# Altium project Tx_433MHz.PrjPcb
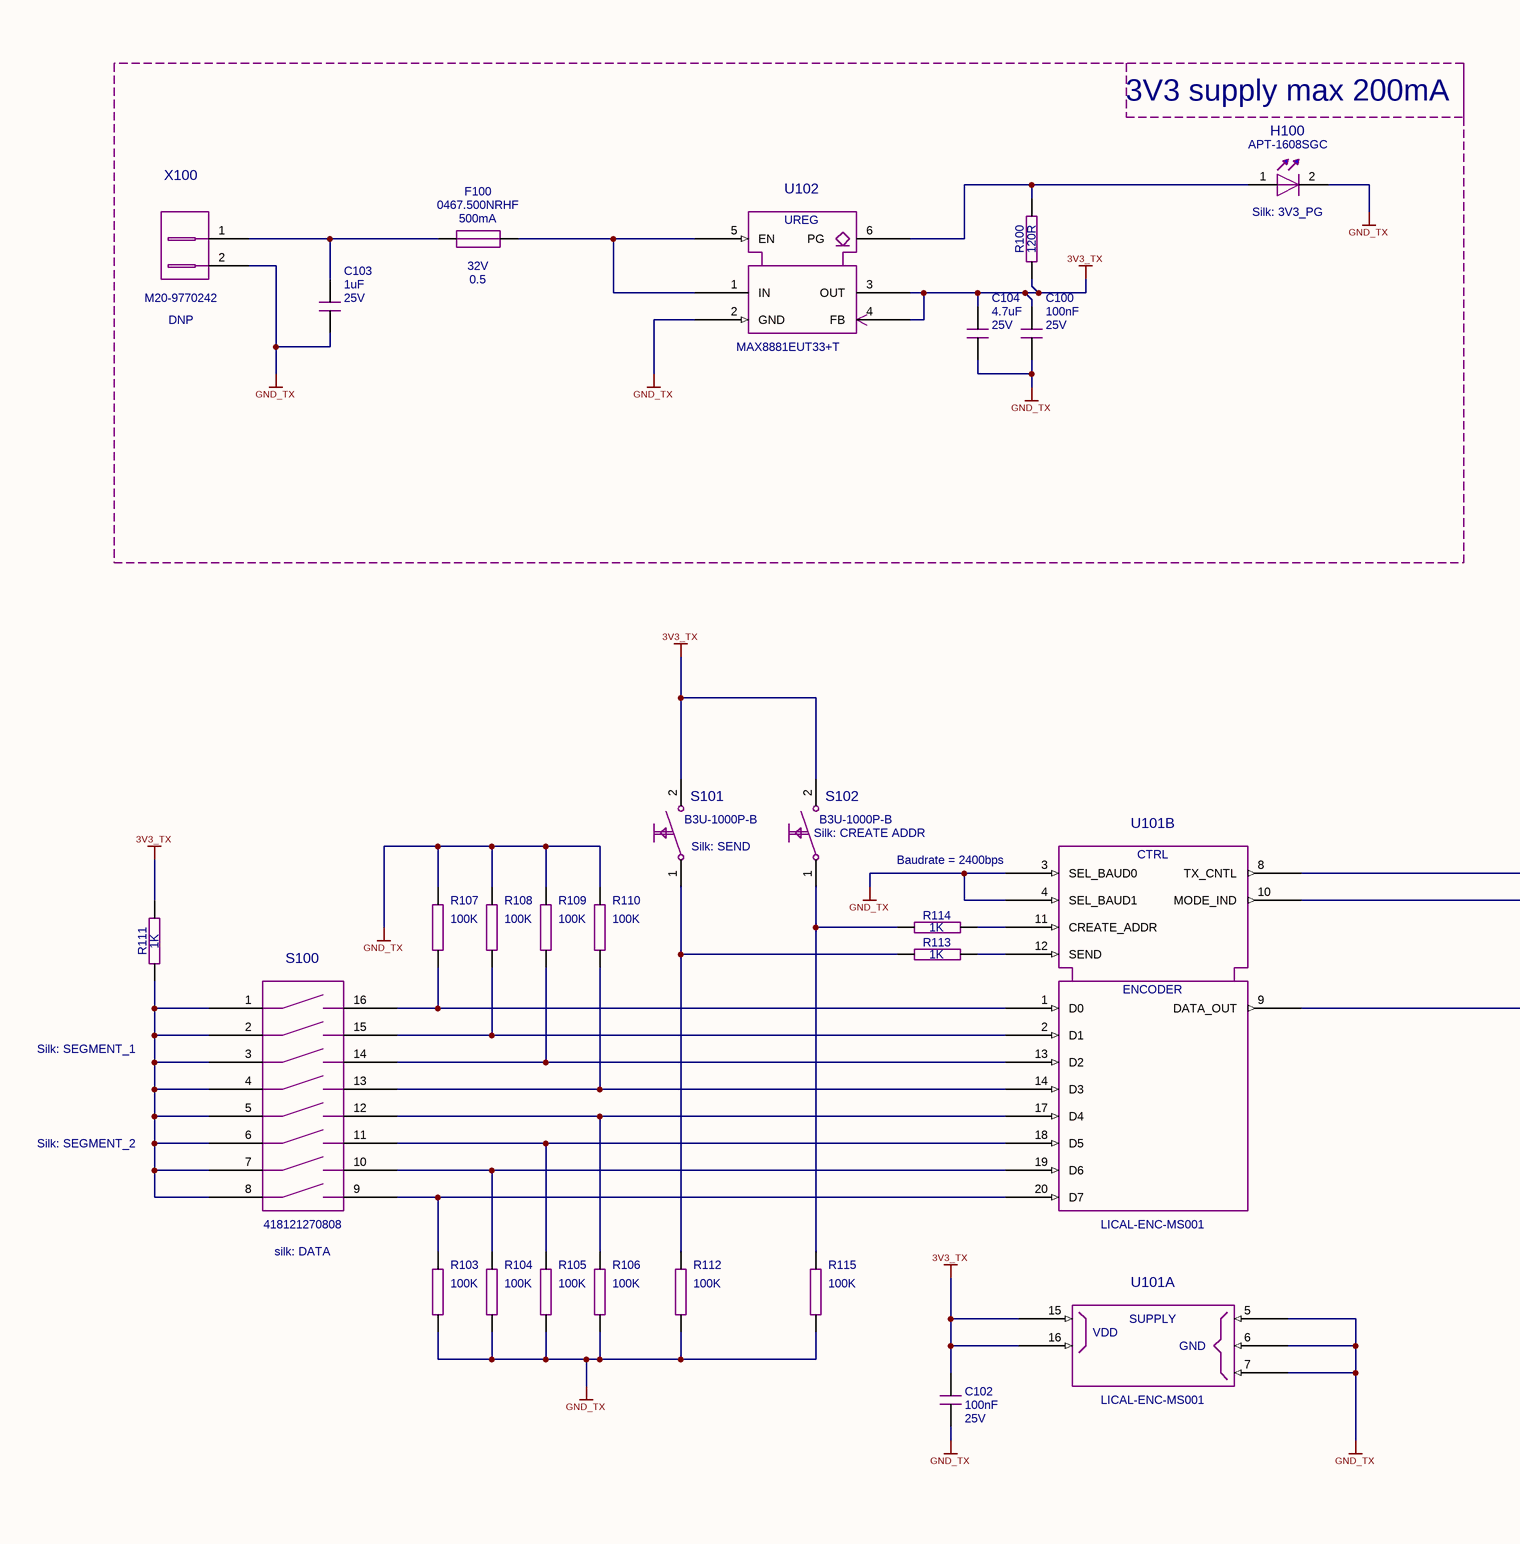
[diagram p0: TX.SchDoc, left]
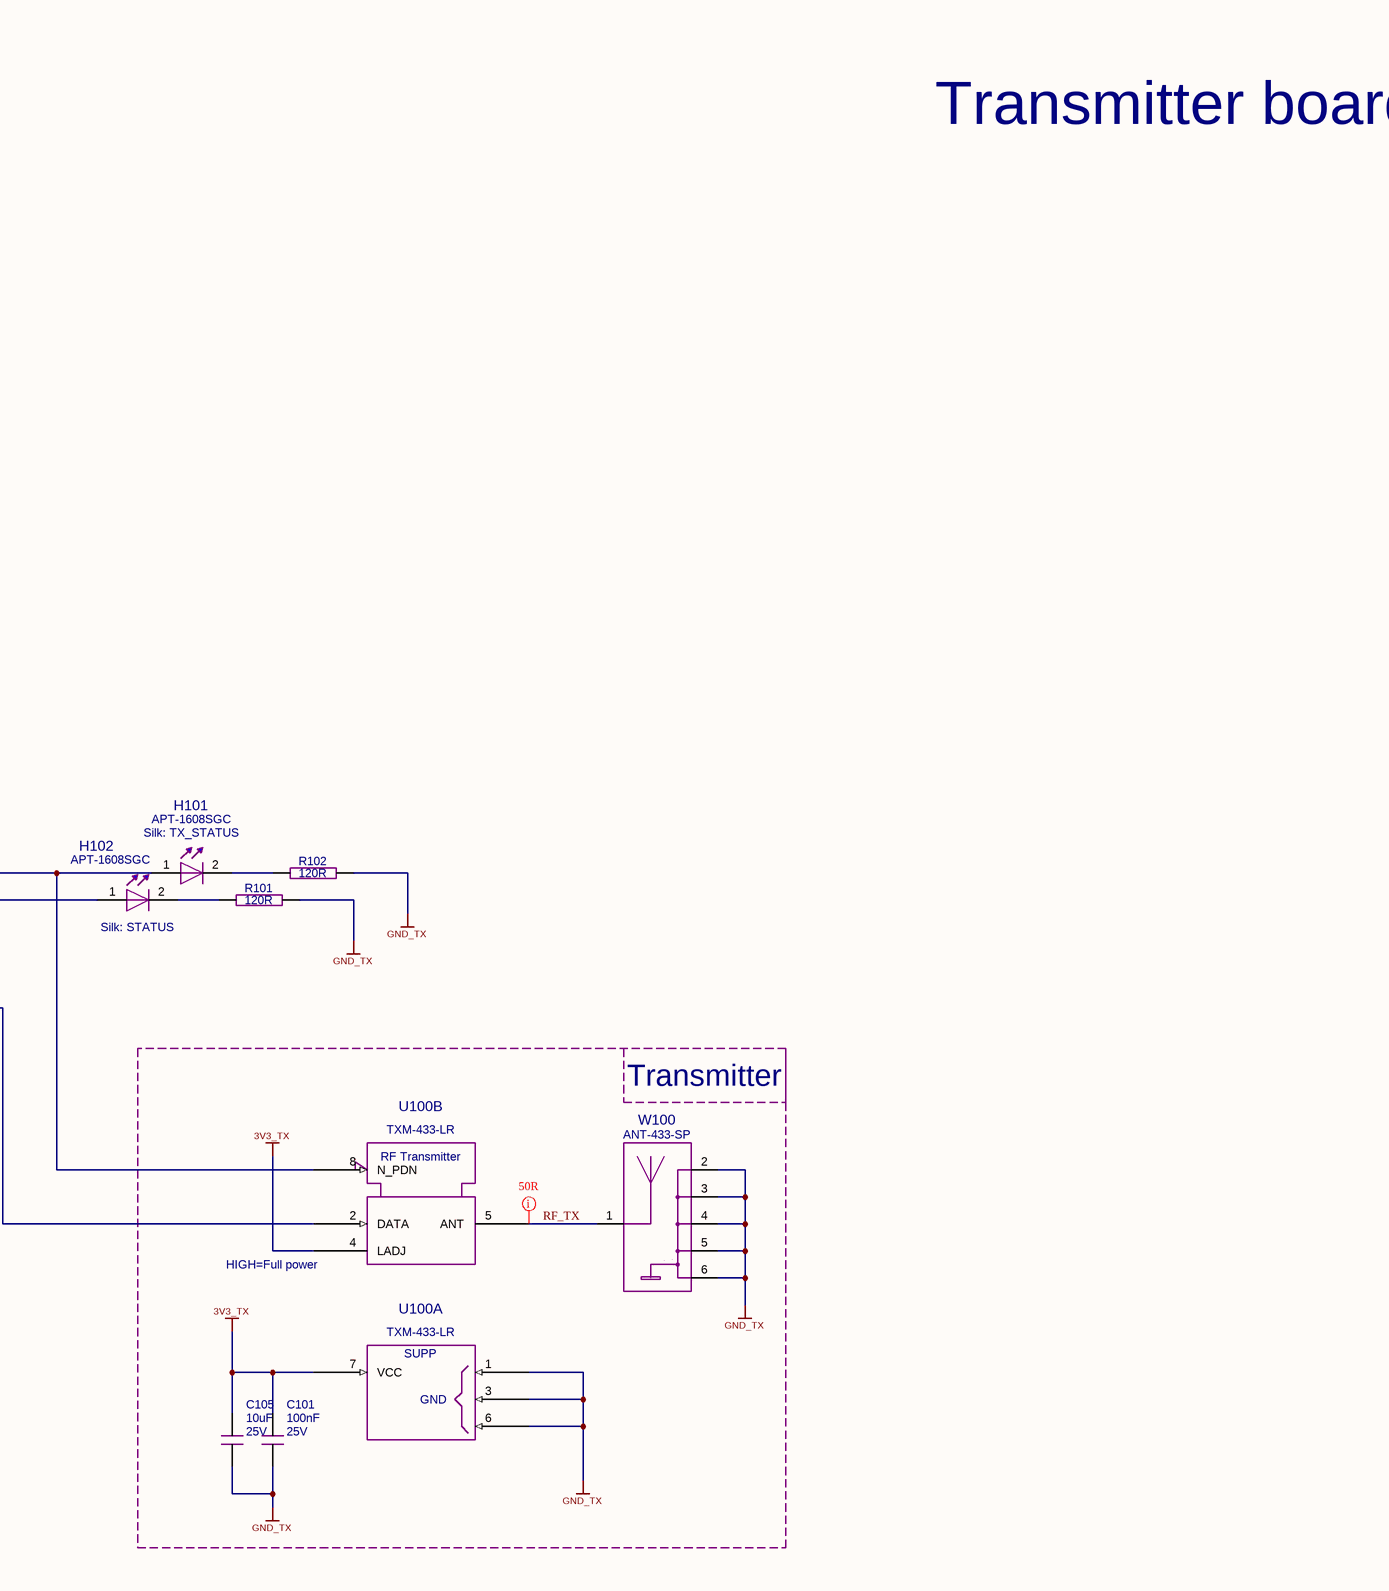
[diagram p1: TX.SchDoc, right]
1 sheet, 34 parts. Net scope: hierarchical (ports join the sheet entries above them; power ports are global).
Board files: Tx_433MHz.PcbDoc, Tx_433MHz-Placed.PcbDoc, Tx_433MHz-Routed.PcbDoc

## Sheet TX.SchDoc
size 594 x 420 mm; APPROVED: Yes; Border_Classification: ?; CmpIndex: 0; ENGINEER: KuRe/SnLe; REVIEWED: Yes; REVISION: 2.0; SymIndex: 1

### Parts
C100  value 100nF  Voltage: 25V  [CAPC1608X90N_0603_GENERIC]  (hidden comment: C_0603_1608X90_GENERIC)
C101  value 100nF  Voltage: 25V  [CAPC1608X90N_0603_GENERIC]  (hidden comment: C_0603_1608X90_GENERIC)
C102  value 100nF  Voltage: 25V  [CAPC1608X90N_0603_GENERIC]  (hidden comment: C_0603_1608X90_GENERIC)
C103  value 1uF  Voltage: 25V  [CAPC2012X150N_0805_GENERIC]  (hidden comment: C_0805_2012X150_GENERIC)
C104  value 4.7uF  Voltage: 25V  [CAPC1608X105N]  (hidden comment: CL10A226MP8NUNE)
C105  value 10uF  Voltage: 25V  [CAPC3216X190N_1206_GENERIC]  (hidden comment: C_1206_3216X190_GENERIC)
F100  value 500mA  Current: 0.5  MPN: 0467.500NRHF  Voltage: 32V  [RESC1608X60N_0603_GENERIC]  (hidden comment: 0467XXXX)
H100  MPN: APT-1608SGC  [LEDC1608X110N]  (hidden comment: KP-1608SGC)
H101  MPN: APT-1608SGC  [LEDC1608X110N]  (hidden comment: KP-1608SGC)
H102  MPN: APT-1608SGC  [LEDC1608X110N]  (hidden comment: KP-1608SGC)
R100  value 120R  [RESC2012X60N_0805_GENERIC]  (hidden comment: R_0805_2012X60_GENERIC)
R101  value 120R  [RESC2012X60N_0805_GENERIC]  (hidden comment: R_0805_2012X60_GENERIC)
R102  value 120R  [RESC2012X60N_0805_GENERIC]  (hidden comment: R_0805_2012X60_GENERIC)
R103  value 100K  [RESC2012X60N_0805_GENERIC]  (hidden comment: R_0805_2012X60_GENERIC)
R104  value 100K  [RESC2012X60N_0805_GENERIC]  (hidden comment: R_0805_2012X60_GENERIC)
R105  value 100K  [RESC2012X60N_0805_GENERIC]  (hidden comment: R_0805_2012X60_GENERIC)
R106  value 100K  [RESC2012X60N_0805_GENERIC]  (hidden comment: R_0805_2012X60_GENERIC)
R107  value 100K  [RESC2012X60N_0805_GENERIC]  (hidden comment: R_0805_2012X60_GENERIC)
R108  value 100K  [RESC2012X60N_0805_GENERIC]  (hidden comment: R_0805_2012X60_GENERIC)
R109  value 100K  [RESC2012X60N_0805_GENERIC]  (hidden comment: R_0805_2012X60_GENERIC)
R110  value 100K  [RESC2012X60N_0805_GENERIC]  (hidden comment: R_0805_2012X60_GENERIC)
R111  value 1K  [RESC2012X60N_0805_GENERIC]  (hidden comment: R_0805_2012X60_GENERIC)
R112  value 100K  [RESC2012X60N_0805_GENERIC]  (hidden comment: R_0805_2012X60_GENERIC)
R113  value 1K  [RESC2012X60N_0805_GENERIC]  (hidden comment: R_0805_2012X60_GENERIC)
R114  value 1K  [RESC2012X60N_0805_GENERIC]  (hidden comment: R_0805_2012X60_GENERIC)
R115  value 100K  [RESC2012X60N_0805_GENERIC]  (hidden comment: R_0805_2012X60_GENERIC)
S100  418121270808  [WE_418121270808]
S101  MPN: B3U-1000P-B  [OMRON_B3U_1000P_B]  (hidden comment: B3U_1000P_B)
S102  MPN: B3U-1000P-B  [OMRON_B3U_1000P_B]  (hidden comment: B3U_1000P_B)
U100  TXM-433-LR  [LINX_TXM-433-LR]  (parts A,B of 2)
U101  LICAL-ENC-MS001  [SOP65P780X200-20N]  (parts A,B of 2)
U102  MPN: MAX8881EUT33+T  [SOT95P280X100-6N]  (hidden comment: MAX8881EU)
W100  ANT-433-SP  [LINX_ANT-433-SP]
X100  MPN: M20-9770242  Place: DNP  [HARWIN_M20_9770242]  (hidden comment: M20_9770242)

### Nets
3V3_TX: C100.1(P) C101.1(P) C102.1(P) C104.1(P) C105.1(P) R100.1(P) R111.2(M) S101.2(S2) S102.2(S2) U100.4(LADJ) U100.7(VCC) U101.15(VDD1) U101.16(VDD2) U102.3(OUT) U102.4(FB)
GND_TX: C100.2(M) C101.2(M) C102.2(M) C103.2(M) C104.2(M) C105.2(M) H100.2(K) R101.2(M) R102.2(M) R103.1(P) R104.1(P) R105.1(P) R106.1(P) R107.2(M) R108.2(M) R109.2(M) R110.2(M) R112.1(P) R115.1(P) U100.1(GND1) U100.3(GND2) U100.6(GND3) U101.3(SEL_BAUD0) U101.4(SEL_BAUD1) U101.5(GND1) U101.6(GND2) U101.7(GND3) U102.2(GND) W100.2(GND1) W100.3(GND2) W100.4(GND3) W100.5(GND4) W100.6(GND5) X100.2(P2)
RF_TX: U100.5(ANT) W100.1(ANT)
NetC103_1: C103.1(P) F100.1(A) X100.1(P1)
NetF100_2: F100.2(B) U102.1(IN) U102.5(EN)
NetH100_1: H100.1(A) R100.2(M) U102.6(PG)
NetH101_1: H101.1(A) U100.8(N_PDN) U101.8(TX_CNTL)
NetH101_2: H101.2(K) R102.1(P)
NetH102_1: H102.1(A) U101.10(MODE_IND)
NetH102_2: H102.2(K) R101.1(P)
NetR103_2: R103.2(M) S100.9(S8_2) U101.20(D7)
NetR104_2: R104.2(M) S100.10(S7_2) U101.19(D6)
NetR105_2: R105.2(M) S100.11(S6_2) U101.18(D5)
NetR106_2: R106.2(M) S100.12(S5_2) U101.17(D4)
NetR107_1: R107.1(P) S100.16(S1_2) U101.1(D0)
NetR108_1: R108.1(P) S100.15(S2_2) U101.2(D1)
NetR109_1: R109.1(P) S100.14(S3_2) U101.13(D2)
NetR110_1: R110.1(P) S100.13(S4_2) U101.14(D3)
NetR111_1: R111.1(P) S100.1(S1_1) S100.2(S2_1) S100.3(S3_1) S100.4(S4_1) S100.5(S5_1) S100.6(S6_1) S100.7(S7_1) S100.8(S8_1)
NetR112_2: R112.2(M) R113.1(P) S101.1(S1)
NetR113_2: R113.2(M) U101.12(SEND)
NetR114_1: R114.1(P) R115.2(M) S102.1(S1)
NetR114_2: R114.2(M) U101.11(CREATE_ADDR)
NetU100_2: U100.2(DATA) U101.9(DATA_OUT)

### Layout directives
net class 50R: RF_TX

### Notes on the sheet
- 3V3 supply max 200mA
- Transmitter board
- (near H100) Silk: 3V3_PG
- (near S101) Silk: SEND
- (near S102) Silk: CREATE ADDR
- (near H101) Silk: TX_STATUS
- Baudrate = 2400bps
- (near H102) Silk: STATUS
- Silk: SEGMENT_1
- Transmitter
- Silk: SEGMENT_2
- (near S100) silk: DATA
- (near U100) HIGH=Full power

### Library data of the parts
C100 = C_0603_1608X90_GENERIC: 100nF 25V 10%; Manufacturer: MURATA; MPN: GRM188R71E104KA01D; Part Name: Ceramic chip capacitor 0603-1608x90, generic; Parts: 1; Capacitance: 100000; CmpIndex: 9; Dielectric: X7R; DXDB_LIBNAME: Capacitor; Level: STD; Ref Designator: C100; SymIndex: 23; Tolerance: 10; Type: Ceramic; Valid: -1
C101 = C_0603_1608X90_GENERIC: 100nF 25V 10%; Manufacturer: MURATA; MPN: GRM188R71E104KA01D; Part Name: Ceramic chip capacitor 0603-1608x90, generic; Parts: 1; Capacitance: 100000; CmpIndex: 36; Dielectric: X7R; DXDB_LIBNAME: Capacitor; Level: STD; Ref Designator: C101; SymIndex: 23; Tolerance: 10; Type: Ceramic; Valid: -1
C102 = C_0603_1608X90_GENERIC: 100nF 25V 10%; Manufacturer: MURATA; MPN: GRM188R71E104KA01D; Part Name: Ceramic chip capacitor 0603-1608x90, generic; Parts: 1; Capacitance: 100000; CmpIndex: 37; Dielectric: X7R; DXDB_LIBNAME: Capacitor; Level: STD; Ref Designator: C102; SymIndex: 23; Tolerance: 10; Type: Ceramic; Valid: -1
C103 = C_0805_2012X150_GENERIC: 1µF 25V 10%; Manufacturer: AVX; MPN: 08053C105K4Z2A; Part Name: Ceramic chip capacitor 0805-2012x150, generic; Parts: 1; Capacitance: 1000000; CmpIndex: 14; Dielectric: X7R; DXDB_LIBNAME: Capacitor; Level: STD; Ref Designator: C103; SymIndex: 23; Tolerance: 10; Type: Ceramic; Valid: -1
C104 = CL10A226MP8NUNE: 4.7uF 25V 10%; Alternate Manufacturer: SAMSUNG; Alternate MPN: CL10A475KA8NQNC; Manufacturer: AVX; MPN: 06033D475KAT2A; Part Name: CAP 22uF 10V 0603 X5R; Parts: 1; Capacitance: 4700000; CmpIndex: 15; Dielectric: X5R; DXDB_LIBNAME: Capacitor; Level: STD; Ref Designator: C104; SymIndex: 23; Tolerance: 10; Type: Ceramic; Valid: 0
C105 = C_1206_3216X190_GENERIC: 10uF 25V 10%; Manufacturer: AVX; MPN: 12063C106KAT2A; Part Name: Cheramic chip capacitor 1206-3216x190, generic; Parts: 1; Capacitance: 10000000; CmpIndex: 45; Dielectric: X7R; DXDB_LIBNAME: Capacitor; Level: STD; Max Temp: +125; Min Temp: -55; Ref Designator: C105; SymIndex: 23; Tolerance: 10; Type: Ceramic; Valid: -1
F100 = 0467XXXX: Thin film 0603 fuse very fast acting; Manufacturer: LITTELFUSE; Part Name: Thin film 0603 very fast acting; CmpIndex: 56; Level: STD; Max Temp: +90; Min Temp: -55; Ref Designator: F100; SymIndex: 25; Valid: -1
H100 = KP-1608SGC: LED Green; Manufacturer: KINGBRIGHT; Part Name: SMD LED lamp, Green; Parts: 1; CmpIndex: 57; Current: 20mA; DXDB_LIBNAME: Diode; Level: STD; Ref Designator: H100; SymIndex: 29; Valid: -1
H101 = KP-1608SGC: LED Green; Manufacturer: KINGBRIGHT; Part Name: SMD LED lamp, Green; Parts: 1; CmpIndex: 11; Current: 20mA; DXDB_LIBNAME: Diode; Level: STD; Ref Designator: H101; SymIndex: 29; Valid: -1
H102 = KP-1608SGC: LED Green; Manufacturer: KINGBRIGHT; Part Name: SMD LED lamp, Green; Parts: 1; CmpIndex: 39; Current: 20mA; DXDB_LIBNAME: Diode; Level: STD; Ref Designator: H102; SymIndex: 29; Valid: -1
R100 = R_0805_2012X60_GENERIC: 0.125W 5% 120R 50V; Manufacturer: YAGEO; MPN: RC0805JR-07120RL; Part Name: resistor_0805-2012x60 generic; CmpIndex: 43; DXDB_LIBNAME: Resistor_0805; Level: STD; Ref Designator: R100; SymIndex: 28; Valid: -1
R101 = R_0805_2012X60_GENERIC: 0.125W 5% 120R 50V; Manufacturer: YAGEO; MPN: RC0805JR-07120RL; Part Name: resistor_0805-2012x60 generic; CmpIndex: 16; DXDB_LIBNAME: Resistor_0805; Level: STD; Ref Designator: R101; SymIndex: 28; Valid: -1
R102 = R_0805_2012X60_GENERIC: 0.125W 5% 120R 50V; Manufacturer: YAGEO; MPN: RC0805JR-07120RL; Part Name: resistor_0805-2012x60 generic; CmpIndex: 38; DXDB_LIBNAME: Resistor_0805; Level: STD; Ref Designator: R102; SymIndex: 28; Valid: -1
R103 = R_0805_2012X60_GENERIC: 0.125W 5% 100K 50V; Manufacturer: YAGEO; MPN: RC0805JR-07100KL; Part Name: resistor_0805-2012x60 generic; CmpIndex: 25; DXDB_LIBNAME: Resistor_0805; Level: STD; Ref Designator: R103; SymIndex: 28; Valid: -1
R104 = R_0805_2012X60_GENERIC: 0.125W 5% 100K 50V; Manufacturer: YAGEO; MPN: RC0805JR-07100KL; Part Name: resistor_0805-2012x60 generic; CmpIndex: 26; DXDB_LIBNAME: Resistor_0805; Level: STD; Ref Designator: R104; SymIndex: 28; Valid: -1
R105 = R_0805_2012X60_GENERIC: 0.125W 5% 100K 50V; Manufacturer: YAGEO; MPN: RC0805JR-07100KL; Part Name: resistor_0805-2012x60 generic; CmpIndex: 27; DXDB_LIBNAME: Resistor_0805; Level: STD; Ref Designator: R105; SymIndex: 28; Valid: -1
R106 = R_0805_2012X60_GENERIC: 0.125W 5% 100K 50V; Manufacturer: YAGEO; MPN: RC0805JR-07100KL; Part Name: resistor_0805-2012x60 generic; CmpIndex: 28; DXDB_LIBNAME: Resistor_0805; Level: STD; Ref Designator: R106; Valid: -1
R107 = R_0805_2012X60_GENERIC: 0.125W 5% 100K 50V; Manufacturer: YAGEO; MPN: RC0805JR-07100KL; Part Name: resistor_0805-2012x60 generic; CmpIndex: 29; DXDB_LIBNAME: Resistor_0805; Level: STD; Ref Designator: R107; SymIndex: 28; Valid: -1
R108 = R_0805_2012X60_GENERIC: 0.125W 5% 100K 50V; Manufacturer: YAGEO; MPN: RC0805JR-07100KL; Part Name: resistor_0805-2012x60 generic; CmpIndex: 30; DXDB_LIBNAME: Resistor_0805; Level: STD; Ref Designator: R108; SymIndex: 28; Valid: -1
R109 = R_0805_2012X60_GENERIC: 0.125W 5% 100K 50V; Manufacturer: YAGEO; MPN: RC0805JR-07100KL; Part Name: resistor_0805-2012x60 generic; CmpIndex: 31; DXDB_LIBNAME: Resistor_0805; Level: STD; Ref Designator: R109; SymIndex: 28; Valid: -1
R110 = R_0805_2012X60_GENERIC: 0.125W 5% 100K 50V; Manufacturer: YAGEO; MPN: RC0805JR-07100KL; Part Name: resistor_0805-2012x60 generic; CmpIndex: 32; DXDB_LIBNAME: Resistor_0805; Level: STD; Ref Designator: R110; SymIndex: 28; Valid: -1
R111 = R_0805_2012X60_GENERIC: Resistor_1K_1%_0805; Manufacturer: MULTICOMP; MPN: MCPWR05FTEW1001; Part Name: resistor_0805-2012x60 generic; CmpIndex: 13; DXDB_LIBNAME: Resistor_0805; Level: STD; Ref Designator: R111; SymIndex: 28; Tolerance: 1%; Valid: -1
R112 = R_0805_2012X60_GENERIC: 0.125W 5% 100K 50V; Manufacturer: YAGEO; MPN: RC0805JR-07100KL; Part Name: resistor_0805-2012x60 generic; CmpIndex: 49; DXDB_LIBNAME: Resistor_0805; Level: STD; Ref Designator: R112; SymIndex: 28; Valid: -1
R113 = R_0805_2012X60_GENERIC: Resistor_1K_1%_0805; Manufacturer: MULTICOMP; MPN: MCPWR05FTEW1001; Part Name: resistor_0805-2012x60 generic; CmpIndex: 47; DXDB_LIBNAME: Resistor_0805; Level: STD; Ref Designator: R113; SymIndex: 28; Tolerance: 1%; Valid: -1
R114 = R_0805_2012X60_GENERIC: Resistor_1K_1%_0805; Manufacturer: MULTICOMP; MPN: MCPWR05FTEW1001; Part Name: resistor_0805-2012x60 generic; CmpIndex: 50; DXDB_LIBNAME: Resistor_0805; Level: STD; Ref Designator: R114; SymIndex: 28; Tolerance: 1%; Valid: -1
R115 = R_0805_2012X60_GENERIC: 0.125W 5% 100K 50V; Manufacturer: YAGEO; MPN: RC0805JR-07100KL; Part Name: resistor_0805-2012x60 generic; CmpIndex: 52; DXDB_LIBNAME: Resistor_0805; Level: STD; Ref Designator: R115; SymIndex: 28; Valid: -1
S100 = 418121270808: Dip Switch SPST 8 Position Surface Mount Slide (Standard) Actuator 25mA 24VDC; Manufacturer: WURTH ELEKTRONIK; CmpIndex: 1; Contacts: 8; Level: STD; Max Temp: 85; Min Temp: -40; Ref Designator: S100; SymIndex: 7; Valid: -1; Voltage: 24
S101 = B3U_1000P_B: Ultra-small Tactile Switch; Manufacturer: OMRON; CmpIndex: 2; Level: STD; Max Temp: 0; Ref Designator: S101; SymIndex: 8
S102 = B3U_1000P_B: Ultra-small Tactile Switch; Manufacturer: OMRON; CmpIndex: 51; Contacts: 2; Level: STD; Max Temp: 0; Ref Designator: S102; SymIndex: 8
U100 = TXM-433-LR: LR Series Transmitter, Low Voltage, Low Power; Manufacturer: Linx Technologies; CmpIndex: 4; DXDB_LIBNAME: Module; Level: STD; Max Temp: 85; Min Temp: -40; Quality: Q2; Ref Designator: U100; SymIndex: 10; Valid: 0
U101 = LICAL-ENC-MS001: MS Series Remote Controler Encoder, Low Voltage, Low Power; Manufacturer: LINX TECHNOLOGIES; CmpIndex: 6; DXDB_LIBNAME: IC Generic; Level: STD; Max Temp: 85; Min Temp: -40; Ref Designator: U101; SymIndex: 19; Valid: 0
U102 = MAX8881EU: Low Dropout Linear Regulator with enable and power good, 3.3V, 6 pin SOT23; Manufacturer: MAXIM; Part Name: Low Dropout Linear Regulator, 6 pin SOT23; CmpIndex: 8; DXDB_LIBNAME: IC Power; Level: STD; Max Temp: 85; Min Temp: -40; Output Current: 0.20A; Quality: Q2; Ref Designator: U102; SymIndex: 20; Valid: 0; Vin Max: 12V; Vin Min: 4.3V; Vout Max: 3.3
W100 = ANT-433-SP: 433MHz 50 Ohm Antenna module; Manufacturer: Linx Technologies; CmpIndex: 55; Level: STD; Max Temp: 130; Min Temp: -40; Quality: Q2; Ref Designator: W100; SymIndex: 37; Valid: 0
X100 = M20_9770242: 1x2 pin 2.54 mm pitch vertical header; Manufacturer: HARWIN; Part Name: STD_HEADER_1x2_2.54_THT; CmpIndex: 7; DXDB_LIBNAME: Connector; Gender: male; Level: STD; Name: 9V in; Ref Designator: X100; SymIndex: 21; Valid: -1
